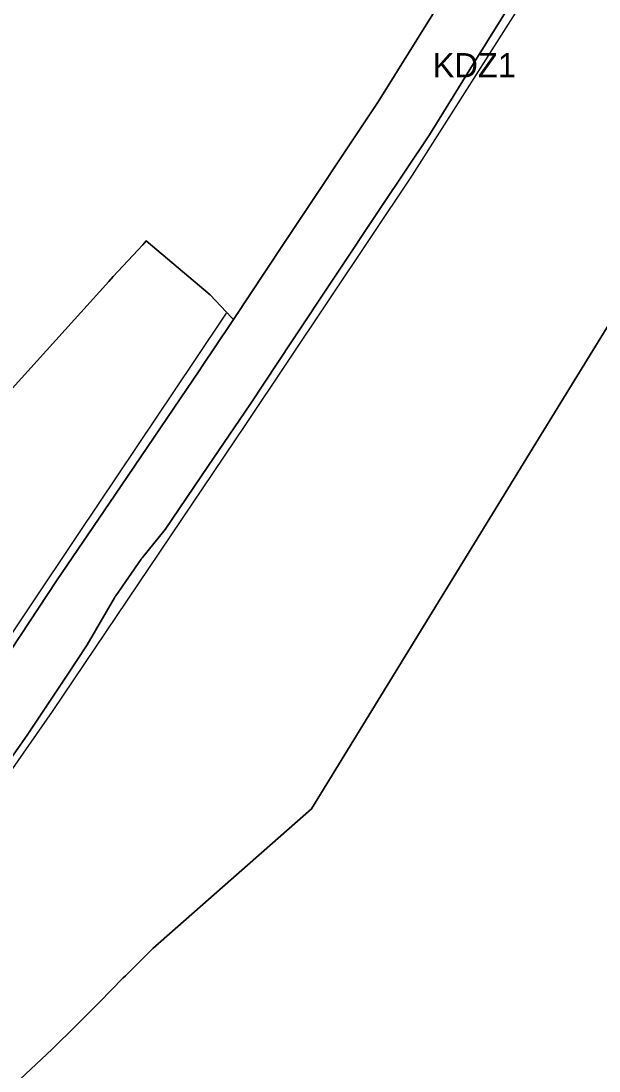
# Model space of a CAD drawing. Extents: x 7439486 to 7443435, y 5551288 to 5554556.
# Drawn here: x 7440818.3 to 7441056.3, y 5552471.7 to 5552903.8 of the extents above; entities that cross this region are included whole.
import ezdxf

# ---------------------------------------------------------------- set-up
doc = ezdxf.new("R2010")
doc.units = 0
for name, color, linetype in [('linie_rozgraniczajace', 7, 'Continuous'), ('linie_zabudowy_nieprzekraczalne', 7, 'Continuous'), ('oznaczenia_przeznaczen', 7, 'Continuous')]:
    doc.layers.add(name, color=color, linetype=linetype)

msp = doc.modelspace()

# ---------------------------------------------------------------- linework, layer by layer
at = {"layer": 'linie_rozgraniczajace'}
for points in [[(7440784.09, 5552438.75), (7440788.29, 5552442.28), (7440796.71, 5552449.34), (7440805.16, 5552456.78), (7440813.62, 5552464.22), (7440822.38, 5552472.46), (7440831.14, 5552480.7), (7440841.01, 5552490.47), (7440850.87, 5552500.24), (7440860.32, 5552509.94), (7440861.3, 5552510.94), (7440872.68, 5552522.16), (7440937.87, 5552579.63), (7441018.76, 5552711.22), (7441030.31, 5552730.01), (7441199.76, 5553005.69)], [(7441199.76, 5553005.69), (7441030.31, 5552730.01), (7441018.76, 5552711.22), (7440937.87, 5552579.63), (7440872.68, 5552522.16), (7440861.3, 5552510.94), (7440860.32, 5552509.94), (7440850.87, 5552500.24), (7440841.01, 5552490.47), (7440831.14, 5552480.7), (7440822.38, 5552472.46), (7440813.62, 5552464.22), (7440805.16, 5552456.78), (7440796.71, 5552449.34), (7440788.29, 5552442.28), (7440784.09, 5552438.75), (7440811.19, 5552387.81), (7440863.47, 5552293.77), (7440866.42, 5552287.9), (7440881.12, 5552260.61), (7440890.03, 5552241.86), (7440895.39, 5552221.28), (7440904.26, 5552212.34)], [(7440811.34, 5552596.15), (7440820.88, 5552609.86), (7440837.33, 5552634.66), (7440845.55, 5552647.05), (7440856.81, 5552666.43), (7440856.92, 5552666.61), (7440857.04, 5552666.8), (7440857.16, 5552666.98), (7440857.28, 5552667.17), (7440857.33, 5552667.25), (7440867.82, 5552682.33), (7440867.95, 5552682.51), (7440868.08, 5552682.68), (7440868.21, 5552682.86), (7440868.32, 5552682.99), (7440877.64, 5552694.59), (7440895.2, 5552720.46), (7440912.76, 5552746.32), (7440929.94, 5552772.12), (7440947.13, 5552797.92), (7440966.8, 5552827.45), (7440986.47, 5552856.97), (7441004.21, 5552885.58), (7441021.96, 5552914.19)], [(7441021.96, 5552914.19), (7441004.21, 5552885.58), (7440986.47, 5552856.97), (7440966.8, 5552827.45), (7440947.13, 5552797.92)], [(7440989.22, 5552908.83), (7440965.44, 5552870.5), (7440926.32, 5552811.77), (7440905.79, 5552780.95), (7440904.96, 5552781.81), (7440896.16, 5552791.04), (7440869.94, 5552813.34), (7440868.45, 5552811.74), (7440866.41, 5552809.54), (7440856.33, 5552798.67), (7440854.44, 5552796.59), (7440806.91, 5552744.07), (7440779.37, 5552717.67), (7440747.23, 5552743.93), (7440715.09, 5552770.19), (7440685.13, 5552792.67), (7440655.16, 5552815.15), (7440624.24, 5552840.11), (7440604.41, 5552810.75), (7440584.98, 5552826.49)], [(7440802.95, 5552628.05), (7440833.02, 5552673.38), (7440856.95, 5552708.64), (7440892.01, 5552760.27), (7440892.72, 5552761.33), (7440904.67, 5552779.27), (7440905.79, 5552780.95), (7440926.32, 5552811.77), (7440965.44, 5552870.5), (7440989.22, 5552908.83)], [(7440806.91, 5552744.07), (7440854.44, 5552796.59), (7440856.33, 5552798.67), (7440866.41, 5552809.54), (7440868.45, 5552811.74), (7440869.94, 5552813.34), (7440896.16, 5552791.04), (7440904.96, 5552781.81), (7440905.79, 5552780.95), (7440904.67, 5552779.27), (7440892.72, 5552761.33), (7440892.01, 5552760.27), (7440856.95, 5552708.64), (7440833.02, 5552673.38), (7440802.95, 5552628.05)], [(7440947.13, 5552797.92), (7440929.94, 5552772.12), (7440912.76, 5552746.32), (7440895.2, 5552720.46), (7440877.64, 5552694.59), (7440868.32, 5552682.99), (7440868.21, 5552682.86), (7440868.08, 5552682.68), (7440867.95, 5552682.51), (7440867.82, 5552682.33), (7440857.33, 5552667.25), (7440857.28, 5552667.17), (7440857.16, 5552666.98), (7440857.04, 5552666.8), (7440856.92, 5552666.61), (7440856.81, 5552666.43), (7440845.55, 5552647.05), (7440837.33, 5552634.66), (7440820.88, 5552609.86), (7440811.34, 5552596.15)]]:
    msp.add_lwpolyline(points, dxfattribs=at)
at = {"layer": 'linie_zabudowy_nieprzekraczalne'}
for points in [[(7440820.32, 5552197.72), (7440815.07, 5552239.39), (7440811.79, 5552259.94), (7440808.51, 5552280.49), (7440806.56, 5552289), (7440803.45, 5552298.21), (7440790.9, 5552325.21), (7440764.52, 5552379.51), (7440742.31, 5552424.31), (7440726.11, 5552457.74), (7440720.01, 5552470.44), (7440715.43, 5552478.46), (7440710.86, 5552486.47), (7440710.78, 5552486.89), (7440710.86, 5552488.83), (7440715.68, 5552492.36), (7440722.02, 5552497.81), (7440737.23, 5552509.98), (7440774.12, 5552538.84), (7440794.17, 5552566.49), (7440831.37, 5552619.67), (7440910.95, 5552737.79), (7440979.56, 5552840.3), (7441030.3, 5552920.28)], [(7440801.18, 5552631.79), (7440842.09, 5552692.97), (7440889.97, 5552764.06), (7440902.99, 5552783.58)]]:
    msp.add_lwpolyline(points, dxfattribs=at)

# ---------------------------------------------------------------- texts
at = {"layer": 'oznaczenia_przeznaczen'}
msp.add_text('KDZ1', height=10, dxfattribs=at).set_placement((7440987.87, 5552880.58))

doc.saveas('drawing.dxf')
